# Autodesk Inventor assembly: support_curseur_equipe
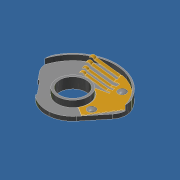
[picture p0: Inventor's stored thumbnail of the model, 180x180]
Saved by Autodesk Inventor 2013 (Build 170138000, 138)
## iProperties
Created: 2011-10
Part Number: support_curseur_equipe
Document SubType Name: Assembly
Designer: didierf
Author: didierf
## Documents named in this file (4)
- D:\_an13-14\FORMULAIRE_2014\Sujet E4 Poissy 2014\Modélisation_7970_shimano_2014\support_curseur_equipe.iam
- D:\_an13-14\FORMULAIRE_2014\Sujet E4 Poissy 2014\Modélisation_7970_shimano_2014\support_curseur.ipt
- support curseur.ipt
- D:\_an13-14\FORMULAIRE_2014\Sujet E4 Poissy 2014\Modélisation_7970_shimano_2014\curseur.ipt
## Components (2 placed, 2 different names)
1. support curseur:1 — Placage:1, Placage:2, Placage:3
2. curseur:1 — Placage:1, Placage:2, Placage:3
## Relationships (3: Mate 3)
- Placage:1 [Mate]: support curseur:1 ↔ curseur:1
- Placage:2 [Mate]: support curseur:1 ↔ curseur:1
- Placage:3 [Mate]: support curseur:1 ↔ curseur:1
